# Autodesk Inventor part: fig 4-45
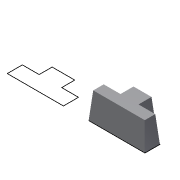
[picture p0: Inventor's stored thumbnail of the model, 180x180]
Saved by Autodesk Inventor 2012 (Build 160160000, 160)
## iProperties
Created: 2004-05
Part Number: fig 4-45
Document SubType Name: Modeling
Designer: CADCIM Technologies
Manufacturer: Standard
Standards Organization: Custom
Density: 1 g/cm^3
Material: Default
Author: CADCIM Technologies
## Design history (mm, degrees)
sketch "Sketch1"
  geometry: L1 (31.783, 34.561)-(31.783, 22.933); L2 (31.783, 22.933)-(16.796, 22.933); L3 (16.796, 22.933)-(16.796, 9.496); L4 (16.796, 9.496)-(66.925, 9.496); L5 (66.925, 9.496)-(66.925, 22.933); L6 (66.925, 22.933)-(51.938, 22.933); L7 (51.938, 22.933)-(51.938, 34.561); L8 (51.938, 34.561)-(31.783, 34.561); L9 (-41.013, 34.561)-(-41.013, 22.933); L10 (-41.013, 22.933)-(-56, 22.933); L11 (-56, 22.933)-(-56, 9.496); L12 (-56, 9.496)-(-5.871, 9.496); L13 (-5.871, 9.496)-(-5.871, 22.933); L14 (-5.871, 22.933)-(-20.858, 22.933); L15 (-20.858, 22.933)-(-20.858, 34.561); L16 (-20.858, 34.561)-(-41.013, 34.561)
  constraints: 32 end point, 10 parallel, 4 equal length, 2 collinear, 2 perpendicular, 2 vertical
extrude "Extrusion1" new body sketch "Sketch1" distance "d0" = 23.25; taper "d1" = -5 deg
body "Solid1"
